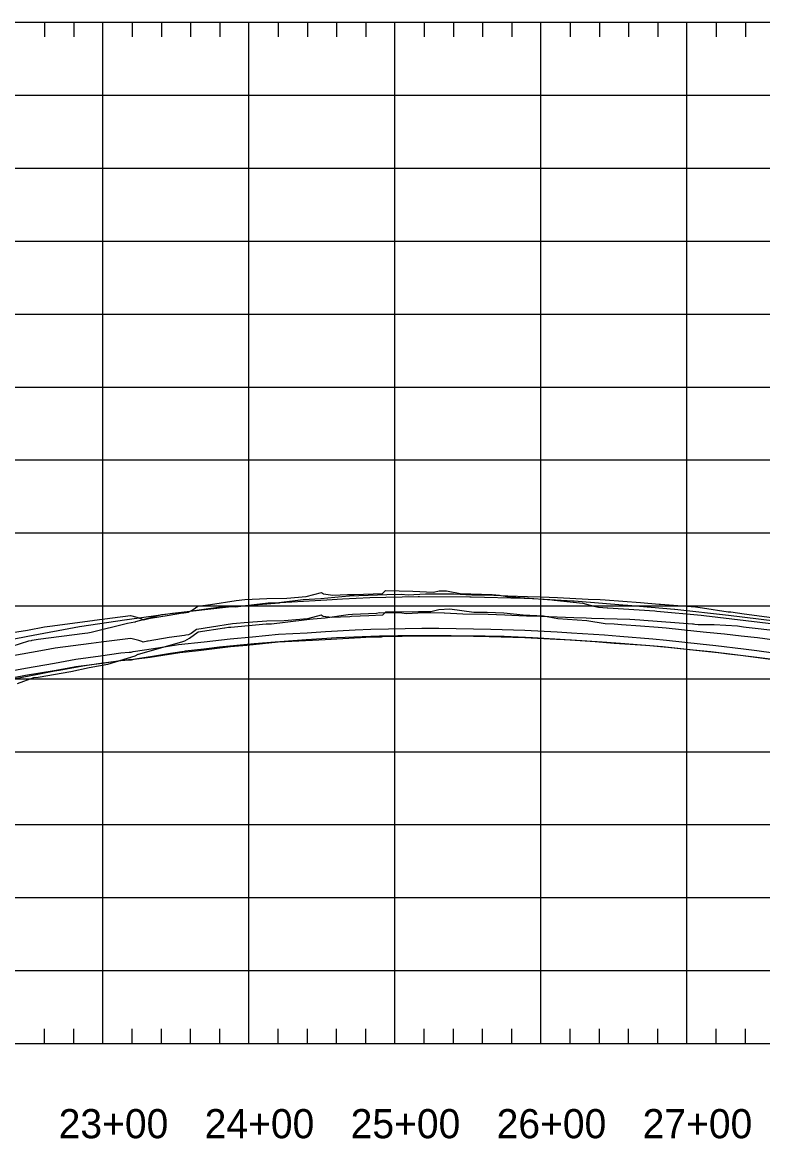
# Model space of a CAD drawing. Extents: x 704797 to 712284, y 374940 to 376945.
# Drawn here: x 709378 to 709886, y 375160 to 375925 of the extents above; entities that cross this region are included whole.
import ezdxf

# ---------------------------------------------------------------- set-up
doc = ezdxf.new("R2010")
doc.units = 0
for name, color, linetype in [('10', 7, 'Continuous'), ('12', 7, 'Continuous'), ('13', 7, 'Continuous'), ('61', 7, 'Continuous'), ('63', 7, 'Continuous'), ('Existing', 7, 'Continuous')]:
    doc.layers.add(name, color=color, linetype=linetype)

msp = doc.modelspace()

# ---------------------------------------------------------------- linework, layer by layer
at = {"layer": '10'}
for points in [[(709893.55, 375501.86), (709882.12, 375503.53), (709870.81, 375504.62), (709859.32, 375505.95), (709846.98, 375507.19), (709840.56, 375507.85), (709819.39, 375510.1), (709813.96, 375510.64), (709801.89, 375511.55), (709788.79, 375512.51), (709783.85, 375512.79), (709777.78, 375513.16), (709765.06, 375515.08), (709745.32, 375516.58), (709735.33, 375518.32), (709721.49, 375518.97), (709708.28, 375520.46), (709696.84, 375521), (709687.69, 375520.99), (709671.24, 375523.17), (709663.8, 375522.74), (709658.32, 375521.38), (709649.82, 375521.4), (709627.24, 375521.23), (709625.07, 375519.03), (709615.82, 375518.51), (709603.92, 375518.05), (709602.87, 375518.01), (709590.3, 375517.43), (709584.54, 375518.18), (709583.14, 375519.02), (709573.89, 375516.54), (709557.82, 375515.2), (709545.86, 375514.95), (709533.13, 375514.15), (709522.34, 375513.11), (709508.01, 375510.76), (709497.86, 375509.24), (709497.71, 375509.22), (709494.02, 375506.59), (709492.22, 375505.62), (709490.39, 375505.35), (709489.57, 375505.21), (709479.04, 375503.66), (709464.71, 375501.22), (709464.28, 375501.15), (709461.29, 375500.51), (709460.41, 375500.97), (709458.22, 375501.64), (709452.75, 375503.08), (709450.81, 375502.83), (709432.35, 375500.5), (709425.65, 375499.58), (709401.02, 375496.41), (709393.54, 375495.16), (709369.47, 375490.67)], [(709375.15, 375472.28), (709386.33, 375476.25), (709389.28, 375476.55), (709411.57, 375480.51), (709424.13, 375483.13), (709437.01, 375485.55), (709455.67, 375491.26), (709457.68, 375492.32), (709458.08, 375492.43), (709487.77, 375500.79), (709489.78, 375501.47), (709492.97, 375503.2), (709498.81, 375507.73), (709516.95, 375510.39), (709517.21, 375510.49), (709519.75, 375510.85), (709521.26, 375510.82), (709545.44, 375513.04), (709547.91, 375513.08), (709549.07, 375513.15), (709558.47, 375514.28), (709575.04, 375516.22), (709577.66, 375516.52), (709585.77, 375517.21), (709601.72, 375519.63), (709604.65, 375519.84), (709620.95, 375520.48), (709623.05, 375520.84), (709638.32, 375520.57), (709641.33, 375520.29), (709653.47, 375520.88), (709667.35, 375520.77), (709667.61, 375520.77), (709680.11, 375520.04), (709697.55, 375519.64), (709709.05, 375519.36), (709718.47, 375518.82), (709723.69, 375518.52), (709723.98, 375518.51), (709733.46, 375518.35), (709756.1, 375517.57), (709764.65, 375517.14), (709768.33, 375517.12), (709794.61, 375516.25), (709801.32, 375515.79), (709804.04, 375515.58), (709837.49, 375513.12), (709838.19, 375513.08), (709839.02, 375512.95), (709841.38, 375512.69), (709852.29, 375512.74), (709868.39, 375511.85), (709872.47, 375511.05), (709874.16, 375510.77), (709896.6, 375508.33)]]:
    msp.add_lwpolyline(points, dxfattribs=at)
at = {"layer": '12'}
for points in [[(709371.86, 375481.1), (709380.57, 375482.81), (709400.4, 375486.17), (709415.05, 375488.93), (709432.09, 375491.15), (709445.96, 375493.3), (709451.62, 375493.67), (709452.93, 375493.77), (709454.26, 375494.14), (709468.4, 375496.2), (709484.15, 375498.74), (709485.32, 375498.92), (709503.05, 375500.86), (709520.86, 375502.94), (709536.06, 375504.14), (709553.85, 375506), (709573.57, 375507.06), (709576.53, 375507.23), (709586.08, 375507.81), (709606.36, 375508.97), (709617.24, 375509.53), (709629.16, 375509.75), (709651.99, 375510.12), (709663.81, 375510.04), (709687.4, 375509.8), (709699.44, 375509.49), (709722.56, 375508.89), (709744.81, 375507.63), (709754.58, 375507.05), (709777.1, 375505.59), (709787.67, 375504.72), (709810.38, 375502.85), (709819.72, 375502.02), (709842.85, 375499.42), (709853.45, 375498.23), (709872.47, 375495.95), (709881.53, 375494.85), (709902.9, 375491.88)], [(709372.3, 375476.25), (709380.62, 375477.87), (709400.18, 375481.15), (709410.39, 375483.05), (709415.01, 375483.9), (709433.1, 375486.15), (709445.49, 375487.98), (709451.82, 375488.34), (709453.33, 375488.44), (709454.86, 375488.85), (709465.91, 375490.37), (709486.34, 375493.51), (709499.13, 375494.93), (709521.11, 375497.52), (709532.12, 375498.39), (709553.67, 375500.67), (709577.13, 375501.94), (709585.9, 375502.46), (709610.14, 375503.83), (709617.39, 375504.19), (709624.49, 375504.32), (709625.2, 375504.33), (709652.22, 375504.85), (709661.15, 375504.82), (709687.52, 375504.65), (709698.1, 375504.41), (709722.55, 375503.85), (709744.38, 375502.69), (709754.61, 375502.12), (709775.58, 375500.82), (709788.12, 375499.83), (709808.19, 375498.23), (709820.5, 375497.18), (709839.79, 375495.06), (709855.15, 375493.38), (709862.13, 375492.56), (709870.32, 375491.58), (709884.02, 375489.91), (709901.14, 375487.53)]]:
    msp.add_lwpolyline(points, dxfattribs=at)
at = {"layer": '13'}
msp.add_lwpolyline([(709894.62, 375488.42), (709885.3, 375489.54), (709849.94, 375493.82), (709838.02, 375495.18), (709816.83, 375497.28), (709805.57, 375498.3), (709783.94, 375499.69), (709770.85, 375500.78), (709746.75, 375502.46), (709735.6, 375503.14), (709727.79, 375503.49), (709708.41, 375504.37), (709695.56, 375504.73), (709672.07, 375504.79), (709659.4, 375504.9), (709635.54, 375504.88), (709623.41, 375504.66), (709623.2, 375504.65), (709593.54, 375503.46), (709583.55, 375502.92), (709572.82, 375502.24), (709548.74, 375500.31), (709537.15, 375499.39), (709513.41, 375497.12), (709502.8, 375495.75), (709489.98, 375494.3), (709489.26, 375494.23), (709479.91, 375492.85), (709467.62, 375490.65), (709457.26, 375489.18), (709455.91, 375488.89), (709454.23, 375488.5), (709452.67, 375488.68), (709430.61, 375485.7), (709420, 375484.11), (709403.72, 375481.15), (709400.42, 375480.56), (709389.1, 375478.49), (709367.65, 375474.26)], dxfattribs=at)
at = {"layer": '61'}
for p, q in [((708133.69, 375925.47), (712133.69, 375925.47)), ((709393.69, 375925.47), (709393.69, 375915.47)), ((709413.69, 375925.47), (709413.69, 375915.47)), ((709433.69, 375225.47), (709433.69, 375925.47)), ((709453.69, 375925.47), (709453.69, 375915.47)), ((709473.69, 375925.47), (709473.69, 375915.47)), ((709493.69, 375925.47), (709493.69, 375915.47)), ((709513.69, 375925.47), (709513.69, 375915.47)), ((709533.69, 375225.47), (709533.69, 375925.47)), ((709553.69, 375925.47), (709553.69, 375915.47)), ((709573.69, 375925.47), (709573.69, 375915.47)), ((709593.69, 375925.47), (709593.69, 375915.47)), ((709613.69, 375925.47), (709613.69, 375915.47)), ((709633.69, 375225.47), (709633.69, 375925.47)), ((709653.69, 375925.47), (709653.69, 375915.47)), ((709673.69, 375925.47), (709673.69, 375915.47)), ((709693.69, 375925.47), (709693.69, 375915.47)), ((709713.69, 375925.47), (709713.69, 375915.47)), ((709733.69, 375225.47), (709733.69, 375925.47)), ((709753.69, 375925.47), (709753.69, 375915.47)), ((709773.69, 375925.47), (709773.69, 375915.47)), ((709793.69, 375925.47), (709793.69, 375915.47)), ((709813.69, 375925.47), (709813.69, 375915.47)), ((709833.69, 375225.47), (709833.69, 375925.47)), ((709853.69, 375925.47), (709853.69, 375915.47)), ((709873.69, 375925.47), (709873.69, 375915.47)), ((708133.69, 375875.47), (712133.69, 375875.47)), ((708133.69, 375825.47), (712133.69, 375825.47)), ((708133.69, 375775.47), (712133.69, 375775.47)), ((708133.69, 375725.47), (712133.69, 375725.47)), ((708133.69, 375675.47), (712133.69, 375675.47)), ((708133.69, 375625.47), (712133.69, 375625.47)), ((708133.69, 375575.47), (712133.69, 375575.47)), ((708133.69, 375525.47), (712133.69, 375525.47)), ((708133.69, 375475.47), (712133.69, 375475.47)), ((708133.69, 375425.47), (712133.69, 375425.47)), ((708133.69, 375375.47), (712133.69, 375375.47)), ((708133.69, 375325.47), (712133.69, 375325.47)), ((708133.69, 375275.47), (712133.69, 375275.47)), ((709393.69, 375225.47), (709393.69, 375235.47)), ((709413.69, 375225.47), (709413.69, 375235.47)), ((709453.69, 375225.47), (709453.69, 375235.47)), ((709473.69, 375225.47), (709473.69, 375235.47)), ((709493.69, 375225.47), (709493.69, 375235.47)), ((709513.69, 375225.47), (709513.69, 375235.47)), ((709553.69, 375225.47), (709553.69, 375235.47)), ((709573.69, 375225.47), (709573.69, 375235.47)), ((709593.69, 375225.47), (709593.69, 375235.47)), ((709613.69, 375225.47), (709613.69, 375235.47)), ((709653.69, 375225.47), (709653.69, 375235.47)), ((709673.69, 375225.47), (709673.69, 375235.47)), ((709693.69, 375225.47), (709693.69, 375235.47)), ((709713.69, 375225.47), (709713.69, 375235.47)), ((709753.69, 375225.47), (709753.69, 375235.47)), ((709773.69, 375225.47), (709773.69, 375235.47)), ((709793.69, 375225.47), (709793.69, 375235.47)), ((709813.69, 375225.47), (709813.69, 375235.47)), ((709853.69, 375225.47), (709853.69, 375235.47)), ((709873.69, 375225.47), (709873.69, 375235.47)), ((708133.69, 375225.47), (712133.69, 375225.47))]:
    msp.add_line(p, q, dxfattribs=at)
at = {"layer": '63'}
for points in [[(709359.95, 375494.2), (709382.85, 375501.39), (709384.4, 375501.69), (709384.74, 375501.76), (709385.12, 375501.83), (709389.25, 375502.58), (709421.21, 375506.69), (709423.25, 375507.02), (709425.59, 375507.35), (709450.46, 375513.61), (709455.57, 375514.45), (709455.6, 375514.52), (709455.9, 375514.58), (709456.03, 375514.6), (709456.12, 375514.64), (709473.98, 375519.45), (709486.14, 375520.87), (709486.32, 375520.86), (709488.34, 375521.11), (709507.58, 375523.9), (709512.86, 375524.51), (709523.1, 375524.94), (709524.47, 375524.81), (709539.11, 375526.53), (709546.92, 375527.46), (709547.01, 375527.45), (709550.23, 375527.5), (709554.17, 375527.75), (709570.78, 375529.75), (709582.95, 375530.51), (709597.28, 375531.92), (709602.56, 375532.31), (709628.01, 375533.3), (709637.86, 375533.54), (709642.82, 375533.09), (709654.51, 375533.65), (709674.33, 375533.62), (709686.24, 375533), (709701.46, 375532.74), (709710.89, 375532.27), (709724.48, 375531.87), (709733.69, 375531.66), (709745, 375531.19), (709766.07, 375529.99), (709774.33, 375529.88), (709777.62, 375529.61), (709801.89, 375527.73), (709814.6, 375526.6), (709815.07, 375526.55), (709815.6, 375526.53), (709839.65, 375524.86), (709844.44, 375524.09), (709862, 375521.44), (709863.7, 375521.25), (709872.78, 375519.96), (709891.75, 375517.5)], [(709368.69, 375506.7), (709381.98, 375508.78), (709393.74, 375510.99), (709397.24, 375511.58), (709426.54, 375515.4), (709427.83, 375515.58), (709452.5, 375518.74), (709456.84, 375517.61), (709460.09, 375516.61), (709461.41, 375515.93), (709465.9, 375516.91), (709466.28, 375516.97), (709479.01, 375519.16), (709488.26, 375520.55), (709488.97, 375520.67), (709492.24, 375521.16), (709495.49, 375522.9), (709498.64, 375525.15), (709507.42, 375526.42), (709524.83, 375529.18), (709530.74, 375529.71), (709545.87, 375530.58), (709559.55, 375530.78), (709572.94, 375531.83), (709583.29, 375534.53), (709584.83, 375533.59), (709591.1, 375532.73), (709601.17, 375533.15), (709603.16, 375533.31), (709603.36, 375533.34), (709605.85, 375533.34), (709625.1, 375533.99), (709627.24, 375536.07), (709645.94, 375535.49), (709659.99, 375534.9), (709664.03, 375535.69), (709669.03, 375535.72), (709678.44, 375533.92), (709700.3, 375533.12), (709705.38, 375532.7), (709710.35, 375531.95), (709741.05, 375529.6), (709742.73, 375529.27), (709762.44, 375527.36), (709769.95, 375525.22), (709773.08, 375524.45), (709779.09, 375524.05), (709779.48, 375524.02), (709811.76, 375522.02), (709813.04, 375521.9), (709843.34, 375518.95), (709845.14, 375518.75), (709893.22, 375513.02)]]:
    msp.add_lwpolyline(points, dxfattribs=at)
at = {"layer": 'Existing'}
msp.add_lwpolyline([(709371.62, 375502.59), (709382.14, 375504.65), (709382.18, 375504.66), (709417.49, 375511.19), (709417.54, 375511.2), (709449.98, 375516.05), (709450.12, 375516.07), (709450.13, 375516.07), (709450.14, 375516.07), (709450.15, 375516.07), (709481.33, 375520.49), (709481.34, 375520.49), (709481.34, 375520.49), (709481.34, 375520.49), (709519.75, 375524.85), (709554.64, 375527.62), (709555.08, 375527.65), (709587.04, 375529.68), (709597.64, 375530.25), (709616.48, 375531.24), (709649.6, 375531.88), (709650.42, 375531.9), (709684.91, 375531.7), (709685.97, 375531.69), (709722.11, 375530.8), (709723.1, 375530.78), (709724.02, 375530.73), (709755.62, 375528.91), (709756.36, 375528.86), (709792.43, 375525.95), (709793.09, 375525.89), (709825.15, 375523.1), (709825.44, 375523.07), (709862.06, 375518.99), (709862.15, 375518.98), (709893.78, 375515.16)], dxfattribs=at)

# ---------------------------------------------------------------- texts
at = {"layer": '61'}
for s, p in [('23+00', (709403.32, 375160.47)), ('24+00', (709503.32, 375160.47)), ('25+00', (709603.32, 375160.47)), ('26+00', (709703.32, 375160.47)), ('27+00', (709803.32, 375160.47))]:
    msp.add_text(s, height=20, dxfattribs=at).set_placement(p)

doc.saveas('drawing.dxf')
